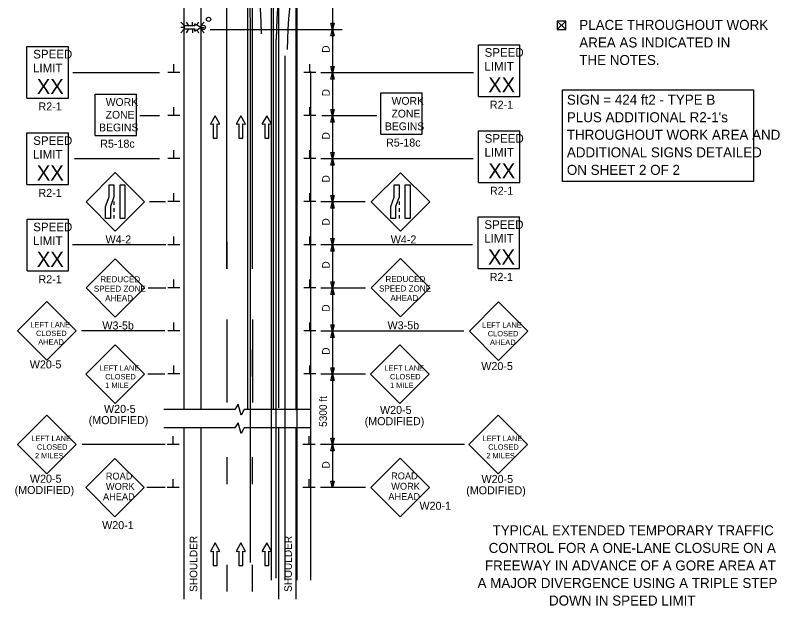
# Model space of a CAD drawing. Extents: x 16335 to 18464, y 5417 to 6974.
# Drawn here: x 16729 to 17439, y 5974 to 6522 of the extents above; entities that cross this region are included whole.
import ezdxf

# ---------------------------------------------------------------- set-up
doc = ezdxf.new("R2010")
doc.units = 0
for name, color, linetype in [('ALI_LEGAL_EX', 7, 'Continuous'), ('BORDER', 7, 'Continuous'), ('MT_SCRATCH_LEVEL_E', 7, 'Continuous'), ('PAVT_EDGE_EX', 7, 'Continuous'), ('TRAFFIC_SIGNS_PR', 7, 'Continuous'), ('TYPICAL_TEXT_DIMEN_EX', 7, 'Continuous'), ('TYPICAL_TEXT_DIMEN_PR', 7, 'Continuous')]:
    doc.layers.add(name, color=color, linetype=linetype)

msp = doc.modelspace()

# ---------------------------------------------------------------- linework, layer by layer
at = {"layer": 'ALI_LEGAL_EX'}
for p, q in [((16944.3, 6974.12), (16944.3, 6155.98)), ((16968.3, 6974.12), (16968.3, 6155.98)), ((16966.29, 6836.53), (16966.29, 5997.6)), ((16990.29, 6836.53), (16990.29, 5997.6)), ((16925.13, 6287.02), (16925.13, 6564.7)), ((16949.13, 6287.02), (16949.13, 6564.7)), ((16947.12, 6014.17), (16947.12, 6514.52)), ((16971.12, 5999.68), (16971.12, 6500.03)), ((16979.26, 5997.6), (16979.26, 6484.64)), ((17003.26, 5997.6), (17003.26, 6470.15)), ((16925.13, 6239.87), (16925.13, 6162.72)), ((16949.13, 6239.87), (16949.13, 6162.72))]:
    msp.add_line(p, q, dxfattribs=at)
for points in [[(16925.13, 6487.02), (16925.13, 6509.03)], [(16949.13, 6487.02), (16949.13, 6509.03)], [(16925.13, 6387.02), (16925.13, 6412.02)], [(16949.13, 6387.02), (16949.13, 6412.02)], [(16925.13, 6312.02), (16925.13, 6287.02)], [(16925.13, 6312.02), (16925.13, 6287.02)], [(16949.13, 6287.02), (16949.13, 6312.02)], [(16925.13, 6212.02), (16925.13, 6187.02)], [(16925.13, 6212.02), (16925.13, 6187.02)], [(16949.13, 6187.02), (16949.13, 6212.02)], [(16925.13, 6112.02), (16925.13, 6087.02)], [(16925.13, 6112.02), (16925.13, 6087.02)], [(16949.13, 6087.02), (16949.13, 6112.02)], [(16925.13, 6012.02), (16925.13, 5987.02)], [(16925.13, 6012.02), (16925.13, 5987.02)], [(16949.13, 5987.02), (16949.13, 6012.02)]]:
    msp.add_lwpolyline(points, dxfattribs=at)
for centre, radius, start, end in [((16583.12, 6514.52), 364, 0, 57.29578), ((16593.27, 6505.1), 364, 0, 57.29578), ((17311.12, 6500.03), 340, 129.56655, 180), ((17321.27, 6490.61), 340, 129.56655, 180)]:
    msp.add_arc(centre, radius, start, end, dxfattribs=at)
at = {"layer": 'MT_SCRATCH_LEVEL_E'}
for p, q in [((16914.27, 6429.09), (16910.15, 6421.85)), ((16918.41, 6421.85), (16914.27, 6429.09)), ((16938.17, 6429.09), (16934.06, 6421.85)), ((16942.32, 6421.85), (16938.17, 6429.09)), ((16962.22, 6429.09), (16958.11, 6421.85)), ((16966.37, 6421.85), (16962.22, 6429.09)), ((16910.64, 6421.16), (16912.41, 6421.48)), ((16912.41, 6421.48), (16912.41, 6408.22)), ((16916.16, 6408.22), (16916.16, 6421.48)), ((16916.16, 6421.48), (16917.93, 6421.16)), ((16934.54, 6421.16), (16936.32, 6421.48)), ((16936.32, 6421.48), (16936.32, 6408.22)), ((16940.06, 6408.22), (16940.06, 6421.48)), ((16940.06, 6421.48), (16941.84, 6421.16)), ((16958.59, 6421.16), (16960.37, 6421.48)), ((16960.37, 6421.48), (16960.37, 6408.22)), ((16964.11, 6408.22), (16964.11, 6421.48)), ((16964.11, 6421.48), (16965.89, 6421.16)), ((16912.41, 6408.22), (16916.16, 6408.22)), ((16936.32, 6408.22), (16940.06, 6408.22)), ((16960.37, 6408.22), (16964.11, 6408.22)), ((16914.27, 6032.27), (16910.15, 6025.03)), ((16918.41, 6025.03), (16914.27, 6032.27)), ((16938.17, 6032.27), (16934.06, 6025.03)), ((16942.32, 6025.03), (16938.17, 6032.27)), ((16962.22, 6032.27), (16958.11, 6025.03)), ((16966.37, 6025.03), (16962.22, 6032.27)), ((16910.64, 6024.34), (16912.41, 6024.65)), ((16912.41, 6024.65), (16912.41, 6011.4)), ((16916.16, 6011.4), (16916.16, 6024.65)), ((16916.16, 6024.65), (16917.93, 6024.34)), ((16934.54, 6024.34), (16936.32, 6024.65)), ((16936.32, 6024.65), (16936.32, 6011.4)), ((16940.06, 6011.4), (16940.06, 6024.65)), ((16940.06, 6024.65), (16941.84, 6024.34)), ((16958.59, 6024.34), (16960.37, 6024.65)), ((16960.37, 6024.65), (16960.37, 6011.4)), ((16964.11, 6011.4), (16964.11, 6024.65)), ((16964.11, 6024.65), (16965.89, 6024.34)), ((16912.41, 6011.4), (16916.16, 6011.4)), ((16936.32, 6011.4), (16940.06, 6011.4)), ((16960.37, 6011.4), (16964.11, 6011.4))]:
    msp.add_line(p, q, dxfattribs=at)
for centre, start, end in [((16910.56, 6421.62), 150.42484, 279.96381), ((16918, 6421.62), 260.03619, 29.77312), ((16934.47, 6421.62), 150.42484, 279.96381), ((16941.91, 6421.62), 260.03619, 29.77312), ((16958.52, 6421.62), 150.42484, 279.96381), ((16965.96, 6421.62), 260.03619, 29.77312), ((16910.56, 6024.8), 150.42484, 279.96381), ((16918, 6024.8), 260.03619, 29.77312), ((16934.47, 6024.8), 150.42484, 279.96381), ((16941.91, 6024.8), 260.03619, 29.77312), ((16958.52, 6024.8), 150.42484, 279.96381), ((16965.96, 6024.8), 260.03619, 29.77312)]:
    msp.add_arc(centre, 0.463, start, end, dxfattribs=at)
at = {"layer": 'PAVT_EDGE_EX'}
for p, q in [((16885.13, 6564.7), (16885.13, 6156.73)), ((16901.13, 6564.7), (16901.13, 6156.73)), ((16973.13, 6564.7), (16973.13, 6157.8)), ((16989.13, 6564.7), (16989.13, 6155.65)), ((16885.13, 6139.09), (16885.13, 5979.91)), ((16901.13, 6139.09), (16901.13, 5979.91)), ((16973.13, 6139.09), (16973.13, 5979.91)), ((16989.13, 6139.09), (16989.13, 5979.91))]:
    msp.add_line(p, q, dxfattribs=at)
at = {"layer": 'TRAFFIC_SIGNS_PR'}
for p, q in [((16885.2, 6513.11), (16882.38, 6515.93)), ((16885.2, 6511.07), (16882.38, 6511.07)), ((16887.5, 6515.93), (16889.13, 6513.11)), ((16893.29, 6513.11), (16893.29, 6515.93)), ((16898.76, 6515.93), (16897.55, 6513.83)), ((16904.19, 6515.92), (16901.37, 6513.11)), ((16901.37, 6511.07), (16904.19, 6511.07)), ((16885.2, 6509.04), (16882.38, 6506.22)), ((16889.15, 6509.04), (16887.52, 6506.22)), ((16893.29, 6509.04), (16893.29, 6506.22)), ((16897.47, 6508.41), (16898.73, 6506.22)), ((16904.19, 6506.22), (16901.37, 6509.04)), ((16739.53, 6493.43), (16777.93, 6493.43)), ((16739.53, 6445.43), (16739.53, 6493.43)), ((16777.93, 6445.43), (16777.93, 6493.43)), ((17158.8, 6495), (17197.2, 6495)), ((17158.8, 6447), (17158.8, 6495)), ((17197.2, 6447), (17197.2, 6495)), ((16802.7, 6410.82), (16802.7, 6449.22)), ((16802.7, 6449.22), (16841.1, 6449.22)), ((16841.1, 6410.82), (16841.1, 6449.22)), ((17068.22, 6411.89), (17068.22, 6450.29)), ((17068.22, 6450.29), (17106.62, 6450.29)), ((17106.62, 6411.89), (17106.62, 6450.29)), ((16739.53, 6445.43), (16777.93, 6445.43)), ((17158.8, 6447), (17197.2, 6447)), ((16739.53, 6413.13), (16777.93, 6413.13)), ((16739.53, 6365.13), (16739.53, 6413.13)), ((16777.93, 6365.13), (16777.93, 6413.13)), ((17068.22, 6411.89), (17106.62, 6411.89)), ((17158.89, 6415.13), (17197.29, 6415.13)), ((17158.89, 6367.13), (17158.89, 6415.13)), ((17197.29, 6367.13), (17197.29, 6415.13)), ((16802.7, 6410.82), (16841.1, 6410.82)), ((16821.54, 6376.2), (16794.39, 6349.05)), ((16848.69, 6349.05), (16821.54, 6376.2)), ((17086.45, 6376.16), (17059.29, 6349)), ((17113.6, 6349), (17086.45, 6376.16)), ((16739.53, 6365.13), (16777.93, 6365.13)), ((17158.89, 6367.13), (17197.29, 6367.13)), ((16794.39, 6349.05), (16821.54, 6321.89)), ((16820.29, 6349.54), (16820.29, 6346.34)), ((16821.54, 6321.89), (16848.69, 6349.05)), ((17059.29, 6349), (17086.45, 6321.85)), ((17085.2, 6349.49), (17085.2, 6346.29)), ((17086.45, 6321.85), (17113.6, 6349)), ((16820.29, 6343.14), (16820.29, 6339.94)), ((17085.2, 6343.09), (17085.2, 6339.89)), ((16820.29, 6336.74), (16820.29, 6333.54)), ((17085.2, 6336.69), (17085.2, 6333.49)), ((17158.65, 6335.1), (17197.05, 6335.1)), ((17158.65, 6287.1), (17158.65, 6335.1)), ((17197.05, 6287.1), (17197.05, 6335.1)), ((16739.55, 6332.91), (16777.95, 6332.91)), ((16739.55, 6284.91), (16739.55, 6332.91)), ((16777.95, 6284.91), (16777.95, 6332.91)), ((16821.58, 6296.28), (16794.42, 6269.13)), ((16848.73, 6269.13), (16821.58, 6296.28)), ((17086.47, 6296.46), (17059.32, 6269.3)), ((17113.63, 6269.3), (17086.47, 6296.46)), ((16739.55, 6284.91), (16777.95, 6284.91)), ((17158.65, 6287.1), (17197.05, 6287.1)), ((16794.42, 6269.13), (16821.58, 6241.97)), ((16821.58, 6241.97), (16848.73, 6269.13)), ((17059.32, 6269.3), (17086.47, 6242.15)), ((17086.47, 6242.15), (17113.63, 6269.3)), ((16757.98, 6256.47), (16730.79, 6229.28)), ((16785.17, 6229.28), (16757.98, 6256.47)), ((17177.59, 6256.22), (17150.41, 6229.03)), ((17204.78, 6229.03), (17177.59, 6256.22)), ((16730.79, 6229.28), (16757.98, 6202.09)), ((16757.98, 6202.09), (16785.17, 6229.28)), ((17150.41, 6229.03), (17177.59, 6201.85)), ((17177.59, 6201.85), (17204.78, 6229.03)), ((16821.33, 6216.22), (16794.14, 6189.04)), ((16848.52, 6189.04), (16821.33, 6216.22)), ((17085.88, 6216.21), (17058.69, 6189.02)), ((17113.07, 6189.02), (17085.88, 6216.21)), ((16794.14, 6189.04), (16821.33, 6161.85)), ((16821.33, 6161.85), (16848.52, 6189.04)), ((17058.69, 6189.02), (17085.88, 6161.83)), ((17085.88, 6161.83), (17113.07, 6189.02)), ((16757.9, 6150.88), (16730.71, 6123.69)), ((16785.09, 6123.69), (16757.9, 6150.88)), ((17177.1, 6150.88), (17149.91, 6123.69)), ((17204.28, 6123.69), (17177.1, 6150.88)), ((16730.71, 6123.69), (16757.9, 6096.51)), ((16757.9, 6096.51), (16785.09, 6123.69)), ((17149.91, 6123.69), (17177.1, 6096.51)), ((17177.1, 6096.51), (17204.28, 6123.69)), ((16821.18, 6110.81), (16794.03, 6083.66)), ((16848.33, 6083.66), (16821.18, 6110.81)), ((17086.19, 6110.96), (17059.04, 6083.81)), ((17113.34, 6083.81), (17086.19, 6110.96)), ((16794.03, 6083.66), (16821.18, 6056.51)), ((16821.18, 6056.51), (16848.33, 6083.66)), ((17059.04, 6083.81), (17086.19, 6056.66)), ((17086.19, 6056.66), (17113.34, 6083.81))]:
    msp.add_line(p, q, dxfattribs=at)
for points in [[(16895.11, 6513.76), (16895.34, 6512.46), (16885.62, 6512.46), (16885.62, 6509.72), (16895.34, 6509.72), (16895.11, 6508.41)], [(16895.61, 6508.06), (16900.92, 6511.07), (16895.61, 6514.11)]]:
    msp.add_lwpolyline(points, dxfattribs=at)
for points in [[(16820.29, 6364.78), (16820.29, 6353.6), (16816.95, 6344.72), (16816.95, 6333.54), (16812.45, 6333.54), (16812.45, 6344.72), (16815.8, 6353.6), (16815.8, 6364.78)], [(16830.43, 6364.78), (16830.43, 6333.54), (16825.94, 6333.54), (16825.94, 6364.78)], [(17085.2, 6364.74), (17085.2, 6353.56), (17081.86, 6344.68), (17081.86, 6333.49), (17077.36, 6333.49), (17077.36, 6344.68), (17080.71, 6353.56), (17080.71, 6364.74)], [(17095.34, 6364.74), (17095.34, 6333.49), (17090.84, 6333.49), (17090.84, 6364.74)]]:
    msp.add_lwpolyline(points, close=True, dxfattribs=at)
for centre in [(16908.21, 6518.62), (16903.24, 6511.12)]:
    msp.add_circle(centre, 2, dxfattribs=at)
for centre, start, end in [((16895.45, 6513.81), 61.48329, 189.95933), ((16895.45, 6508.36), 170.73078, 298.89165)]:
    msp.add_arc(centre, 0.341, start, end, dxfattribs=at)
at = {"layer": 'TYPICAL_TEXT_DIMEN_EX'}
msp.add_lwpolyline([(17236.94, 6453.17), (17414.21, 6453.17), (17414.21, 6367.85), (17236.94, 6367.85)], close=True, dxfattribs=at)
at = {"layer": 'TYPICAL_TEXT_DIMEN_PR'}
for p, q in [((17023.24, 6541.14), (17023.24, 6509.03)), ((17023.24, 6509.03), (17021.67, 6514.9)), ((17021.67, 6514.9), (17023.24, 6514.9)), ((17023.24, 6514.9), (17024.81, 6514.9)), ((17024.81, 6514.9), (17023.24, 6509.03)), ((17232, 6517.04), (17240, 6509.04)), ((17232, 6509.04), (17240, 6517.04)), ((16909.53, 6509.03), (17032.15, 6509.03)), ((17021.67, 6503.17), (17023.24, 6509.03)), ((17023.24, 6509.03), (17023.24, 6469.03)), ((17023.24, 6509.03), (17024.81, 6503.17)), ((17023.24, 6503.17), (17021.67, 6503.17)), ((17024.81, 6503.17), (17023.24, 6503.17)), ((16876.01, 6469.12), (16876.01, 6476.9)), ((17002.26, 6469.12), (17002.26, 6476.9)), ((16862.74, 6469.03), (16781.98, 6469.03)), ((16881.63, 6469.12), (16870.38, 6469.12)), ((17007.88, 6469.12), (16996.63, 6469.12)), ((17154.27, 6469.03), (17012.41, 6469.03)), ((17023.24, 6469.03), (17021.67, 6474.9)), ((17021.67, 6474.9), (17023.24, 6474.9)), ((17021.67, 6463.17), (17023.24, 6469.03)), ((17023.24, 6474.9), (17024.81, 6474.9)), ((17024.81, 6474.9), (17023.24, 6469.03)), ((17023.24, 6469.03), (17023.24, 6429.03)), ((17023.24, 6469.03), (17024.81, 6463.17)), ((17023.24, 6463.17), (17021.67, 6463.17)), ((17024.81, 6463.17), (17023.24, 6463.17)), ((16875.89, 6429.28), (16875.89, 6437.06)), ((17002.26, 6429.28), (17002.26, 6437.06)), ((17023.24, 6429.03), (17021.67, 6434.9)), ((17021.67, 6434.9), (17023.24, 6434.9)), ((17023.24, 6434.9), (17024.81, 6434.9)), ((17024.81, 6434.9), (17023.24, 6429.03)), ((16862.74, 6429.03), (16844.42, 6429.03)), ((16881.52, 6429.28), (16870.27, 6429.28)), ((17007.88, 6429.28), (16996.63, 6429.28)), ((17064.52, 6429.03), (17013.53, 6429.03)), ((17021.67, 6423.17), (17023.24, 6429.03)), ((17023.24, 6429.03), (17023.24, 6389.03)), ((17023.24, 6429.03), (17024.81, 6423.17)), ((17023.24, 6423.17), (17021.67, 6423.17)), ((17024.81, 6423.17), (17023.24, 6423.17)), ((16875.89, 6389.28), (16875.89, 6397.06)), ((17002.26, 6389.28), (17002.26, 6397.06)), ((17023.24, 6389.03), (17021.67, 6394.9)), ((17021.67, 6394.9), (17023.24, 6394.9)), ((17023.24, 6394.9), (17024.81, 6394.9)), ((17024.81, 6394.9), (17023.24, 6389.03)), ((16862.74, 6389.03), (16783.73, 6389.03)), ((16881.52, 6389.28), (16870.27, 6389.28)), ((17007.88, 6389.28), (16996.63, 6389.28)), ((17154.03, 6389.03), (17012.41, 6389.03)), ((17021.67, 6383.17), (17023.24, 6389.03)), ((17023.24, 6389.03), (17023.24, 6349.03)), ((17023.24, 6389.03), (17024.81, 6383.17)), ((17023.24, 6383.17), (17021.67, 6383.17)), ((17024.81, 6383.17), (17023.24, 6383.17)), ((16875.89, 6349.28), (16875.89, 6357.06)), ((17002.26, 6349.28), (17002.26, 6357.06)), ((17023.24, 6349.03), (17021.67, 6354.9)), ((17021.67, 6354.9), (17023.24, 6354.9)), ((17023.24, 6354.9), (17024.81, 6354.9)), ((17024.81, 6354.9), (17023.24, 6349.03)), ((16868.25, 6349.03), (16853.35, 6349.03)), ((16881.52, 6349.28), (16870.27, 6349.28)), ((17007.88, 6349.28), (16996.63, 6349.28)), ((17053.67, 6349.03), (17012.41, 6349.03)), ((17021.67, 6343.17), (17023.24, 6349.03)), ((17023.24, 6349.03), (17023.24, 6309.03)), ((17023.24, 6349.03), (17024.81, 6343.17)), ((17023.24, 6343.17), (17021.67, 6343.17)), ((17024.81, 6343.17), (17023.24, 6343.17)), ((16875.89, 6309.28), (16875.89, 6317.06)), ((17002.26, 6309.28), (17002.26, 6317.06)), ((17023.24, 6309.03), (17021.67, 6314.9)), ((17021.67, 6314.9), (17023.24, 6314.9)), ((17023.24, 6314.9), (17024.81, 6314.9)), ((17024.81, 6314.9), (17023.24, 6309.03)), ((16868.43, 6309.28), (16781.76, 6309.28)), ((16881.52, 6309.28), (16870.27, 6309.28)), ((17007.88, 6309.28), (16996.63, 6309.28)), ((17153.43, 6309.03), (17012.41, 6309.03)), ((17021.67, 6303.17), (17023.24, 6309.03)), ((17023.24, 6309.03), (17023.24, 6269.03)), ((17023.24, 6309.03), (17024.81, 6303.17)), ((17023.24, 6303.17), (17021.67, 6303.17)), ((17024.81, 6303.17), (17023.24, 6303.17)), ((16875.89, 6269.28), (16875.89, 6277.06)), ((17002.26, 6269.28), (17002.26, 6277.06)), ((17023.24, 6269.03), (17021.67, 6274.9)), ((17021.67, 6274.9), (17023.24, 6274.9)), ((17023.24, 6274.9), (17024.81, 6274.9)), ((17024.81, 6274.9), (17023.24, 6269.03)), ((16868.43, 6269.03), (16852.03, 6269.03)), ((16881.52, 6269.28), (16870.27, 6269.28)), ((17007.88, 6269.28), (16996.63, 6269.28)), ((17054.02, 6269.03), (17012.41, 6269.03)), ((17021.67, 6263.17), (17023.24, 6269.03)), ((17023.24, 6263.17), (17021.67, 6263.17)), ((17023.24, 6269.03), (17023.24, 6229.03)), ((17023.24, 6269.03), (17024.81, 6263.17)), ((17024.81, 6263.17), (17023.24, 6263.17)), ((16875.89, 6229.28), (16875.89, 6237.06)), ((17002.26, 6229.28), (17002.26, 6237.06)), ((17023.24, 6229.03), (17021.67, 6234.9)), ((17021.67, 6234.9), (17023.24, 6234.9)), ((17023.24, 6234.9), (17024.81, 6234.9)), ((17024.81, 6234.9), (17023.24, 6229.03)), ((16867.56, 6229.28), (16790.31, 6229.28)), ((16881.52, 6229.28), (16870.27, 6229.28)), ((17007.88, 6229.28), (16996.63, 6229.28)), ((17145.38, 6229.03), (17012.41, 6229.03)), ((17021.67, 6223.17), (17023.24, 6229.03)), ((17023.24, 6229.03), (17023.24, 6189.03)), ((17023.24, 6229.03), (17024.81, 6223.17)), ((17023.24, 6223.17), (17021.67, 6223.17)), ((17024.81, 6223.17), (17023.24, 6223.17)), ((16875.89, 6189.28), (16875.89, 6197.06)), ((17002.26, 6189.28), (17002.26, 6197.06)), ((17023.24, 6189.03), (17021.67, 6194.9)), ((17021.67, 6194.9), (17023.24, 6194.9)), ((17023.24, 6194.9), (17024.81, 6194.9)), ((17024.81, 6194.9), (17023.24, 6189.03)), ((16867.56, 6189.03), (16851.81, 6189.03)), ((16881.52, 6189.28), (16870.27, 6189.28)), ((17007.88, 6189.28), (16996.63, 6189.28)), ((17054.02, 6189.03), (17012.41, 6189.03)), ((17021.67, 6183.17), (17023.24, 6189.03)), ((17023.24, 6189.03), (17023.24, 6123.69)), ((17023.24, 6189.03), (17024.81, 6183.17)), ((17023.24, 6183.17), (17021.67, 6183.17)), ((17024.81, 6183.17), (17023.24, 6183.17)), ((16932.48, 6156.23), (16866.54, 6156.23)), ((16935.74, 6161.03), (16932.48, 6156.23)), ((16938.48, 6151.09), (16935.74, 6161.03)), ((16941.22, 6156.23), (16938.48, 6151.09)), ((17003.55, 6156.23), (16941.22, 6156.23)), ((16935.74, 6143.89), (16932.48, 6139.09)), ((16938.48, 6133.95), (16935.74, 6143.89)), ((16932.48, 6139.09), (16866.54, 6139.09)), ((16941.22, 6139.09), (16938.48, 6133.95)), ((17003.55, 6139.09), (16941.22, 6139.09)), ((16875.34, 6123.69), (16875.34, 6131.48)), ((17001.51, 6123.69), (17001.51, 6131.48)), ((17023.24, 6123.69), (17021.67, 6129.56)), ((17021.67, 6129.56), (17023.24, 6129.56)), ((17023.24, 6129.56), (17024.81, 6129.56)), ((17024.81, 6129.56), (17023.24, 6123.69)), ((16867.85, 6123.69), (16790.89, 6123.69)), ((16880.96, 6123.69), (16869.71, 6123.69)), ((17007.13, 6123.69), (16995.88, 6123.69)), ((17146.06, 6123.69), (17012.13, 6123.69)), ((17021.67, 6117.83), (17023.24, 6123.69)), ((17023.24, 6123.69), (17023.24, 6083.69)), ((17023.24, 6123.69), (17024.81, 6117.83)), ((17023.24, 6117.83), (17021.67, 6117.83)), ((17024.81, 6117.83), (17023.24, 6117.83)), ((16875.34, 6083.69), (16875.34, 6091.48)), ((17001.51, 6083.69), (17001.51, 6091.48)), ((17023.24, 6083.69), (17021.67, 6089.56)), ((17021.67, 6089.56), (17023.24, 6089.56)), ((17023.24, 6089.56), (17024.81, 6089.56)), ((17024.81, 6089.56), (17023.24, 6083.69)), ((16867.85, 6083.69), (16850.95, 6083.69)), ((16880.96, 6083.69), (16869.71, 6083.69)), ((17007.13, 6083.69), (16995.88, 6083.69)), ((17053.96, 6083.69), (17012.13, 6083.69))]:
    msp.add_line(p, q, dxfattribs=at)
msp.add_lwpolyline([(17232, 6517.04), (17232, 6509.04), (17240, 6509.04), (17240, 6517.04)], close=True, dxfattribs=at)

# ---------------------------------------------------------------- texts
at = {"layer": 'BORDER'}
for s, p in [('TYPICAL EXTENDED TEMPORARY TRAFFIC', (17172.02, 6039.3)), ('CONTROL FOR A ONE-LANE CLOSURE ON A', (17168.39, 6023)), ('FREEWAY IN ADVANCE OF A GORE AREA AT', (17164.89, 6006.7)), ('A MAJOR DIVERGENCE USING A TRIPLE STEP', (17158.02, 5990.4)), ('DOWN IN SPEED LIMIT', (17224.39, 5974.11))]:
    msp.add_text(s, height=9.3, dxfattribs=at).set_placement(p)
at = {"layer": 'TRAFFIC_SIGNS_PR'}
for s, height, p in [('SPEED', 8, (16745.3, 6482.29)), ('SPEED', 8, (17164.57, 6483.86)), ('LIMIT', 8, (16745.13, 6469.49)), ('LIMIT', 8, (17164.41, 6471.06)), ('XX', 14.031, (16748.64, 6449.19)), ('XX', 14.031, (17167.91, 6450.76)), ('R2-1', 7.44, (16750.21, 6433.99)), ('WORK', 7.217, (16812.7, 6438.19)), ('WORK', 7.217, (17078.22, 6439.26)), ('R2-1', 7.44, (17169.48, 6435.56)), ('ZONE', 7.217, (16812.59, 6426.38)), ('ZONE', 7.217, (17078.11, 6427.45)), ('BEGINS', 7.217, (16806.51, 6414.57)), ('BEGINS', 7.217, (17072.03, 6415.64)), ('SPEED', 8, (17164.66, 6403.99)), ('SPEED', 8, (16745.3, 6401.99)), ('R5-18c', 7.44, (16807.52, 6399.38)), ('R5-18c', 7.44, (17073.04, 6400.45)), ('LIMIT', 8, (17164.5, 6391.19)), ('LIMIT', 8, (16745.13, 6389.19)), ('XX', 14.031, (17168.01, 6370.89)), ('XX', 14.031, (16748.64, 6368.89)), ('R2-1', 7.44, (17169.57, 6355.69)), ('R2-1', 7.44, (16750.21, 6353.69)), ('SPEED', 8, (16745.32, 6321.78)), ('SPEED', 8, (17164.42, 6323.96)), ('LIMIT', 8, (16745.16, 6308.98)), ('W4-2', 7.44, (16812.5, 6310.45)), ('W4-2', 7.44, (17077.4, 6310.41)), ('LIMIT', 8, (17164.26, 6311.16)), ('XX', 14.031, (16748.67, 6288.67)), ('XX', 14.031, (17167.76, 6290.86)), ('R2-1', 7.44, (16750.23, 6273.47)), ('REDUCED', 5.6, (16807.63, 6274.43)), ('REDUCED', 5.6, (17072.53, 6274.61)), ('R2-1', 7.44, (17169.33, 6275.66)), ('SPEED ZONE', 5.6, (16801.63, 6265.63)), ('SPEED ZONE', 5.6, (17066.52, 6265.81)), ('AHEAD', 5.6, (17077.08, 6257.01)), ('AHEAD', 5.6, (16812.19, 6256.83)), ('LEFT LANE', 5.006, (16742.66, 6232.44)), ('W3-5b', 7.44, (16809.53, 6230.53)), ('W3-5b', 7.44, (17074.43, 6230.71)), ('LEFT LANE', 5.006, (17162.27, 6232.19)), ('CLOSED', 5.006, (16747.9, 6224.43)), ('CLOSED', 5.006, (17167.51, 6224.18)), ('AHEAD', 5.006, (16749.95, 6216.42)), ('AHEAD', 5.006, (17169.57, 6216.18)), ('W20-5', 7.449, (16742.14, 6194.38)), ('W20-5', 7.449, (17161.51, 6192.83)), ('LEFT LANE', 5.006, (16806.94, 6192.19)), ('LEFT LANE', 5.006, (17071.49, 6192.18)), ('CLOSED', 5.006, (16812.16, 6184.19)), ('CLOSED', 5.006, (17076.7, 6184.17)), ('1 MILE', 5.006, (16812.15, 6176.18)), ('1 MILE', 5.006, (17076.7, 6176.16)), ('W20-5', 7.449, (16811.07, 6153.05)), ('W20-5', 7.449, (17067.42, 6152.1)), ('(MODIFIED)', 7.449, (16796.87, 6142.6)), ('(MODIFIED)', 7.449, (17053.22, 6141.65)), ('LEFT LANE', 5.006, (16743.51, 6126.85)), ('LEFT LANE', 5.006, (17162.71, 6126.85)), ('CLOSED', 5.006, (16748.72, 6118.84)), ('CLOSED', 5.006, (17167.92, 6118.84)), ('2 MILES', 5.006, (16746.97, 6110.83)), ('2 MILES', 5.006, (17166.17, 6110.83)), ('W20-5', 7.449, (16742.24, 6088.21)), ('ROAD', 6.4, (16812.72, 6091.19)), ('ROAD', 6.4, (17077.73, 6091.34)), ('W20-5', 7.449, (17161.7, 6087.89)), ('(MODIFIED)', 7.449, (16728.04, 6077.75)), ('WORK', 6.4, (16812.83, 6081.6)), ('WORK', 6.4, (17077.84, 6081.74)), ('(MODIFIED)', 7.449, (17147.5, 6077.44)), ('AHEAD', 6.4, (16810.14, 6071.99)), ('AHEAD', 6.4, (17075.15, 6072.14)), ('W20-1', 7.44, (17104.11, 6063.07)), ('W20-1', 7.44, (16809.35, 6045.07))]:
    msp.add_text(s, height=height, dxfattribs=at).set_placement(p)
at = {"layer": 'TYPICAL_TEXT_DIMEN_EX'}
for s, p in [('PLACE THROUGHOUT WORK', (17252.52, 6508.78)), ('AREA AS INDICATED IN', (17252.52, 6492.48)), ('THE NOTES.', (17252.52, 6476.18)), ('SIGN = 424 ft2 - TYPE B', (17240.99, 6439.34)), ("PLUS ADDITIONAL R2-1's", (17240.99, 6423.04)), ('THROUGHOUT WORK AREA AND', (17240.99, 6406.74)), ('ADDITIONAL SIGNS DETAILED', (17240.99, 6390.44)), ('ON SHEET 2 OF 2', (17240.99, 6374.14))]:
    msp.add_text(s, height=9.3, dxfattribs=at).set_placement(p)
at = {"layer": 'TYPICAL_TEXT_DIMEN_PR'}
for s, p in [('D', (17020.68, 6487.55)), ('D', (17020.68, 6447.12)), ('D', (17020.68, 6407.12)), ('D', (17020.68, 6367.12)), ('D', (17020.68, 6327.12)), ('D', (17020.68, 6287.12)), ('D', (17020.68, 6247.12)), ('D', (17020.68, 6207.12)), ('5300 ft', (17018.06, 6140.07)), ('D', (17020.68, 6101.44)), ('SHOULDER', (16897.69, 5986.81)), ('SHOULDER', (16985.55, 5986.81))]:
    msp.add_text(s, height=7, rotation=90, dxfattribs=at).set_placement(p)

doc.saveas('drawing.dxf')
